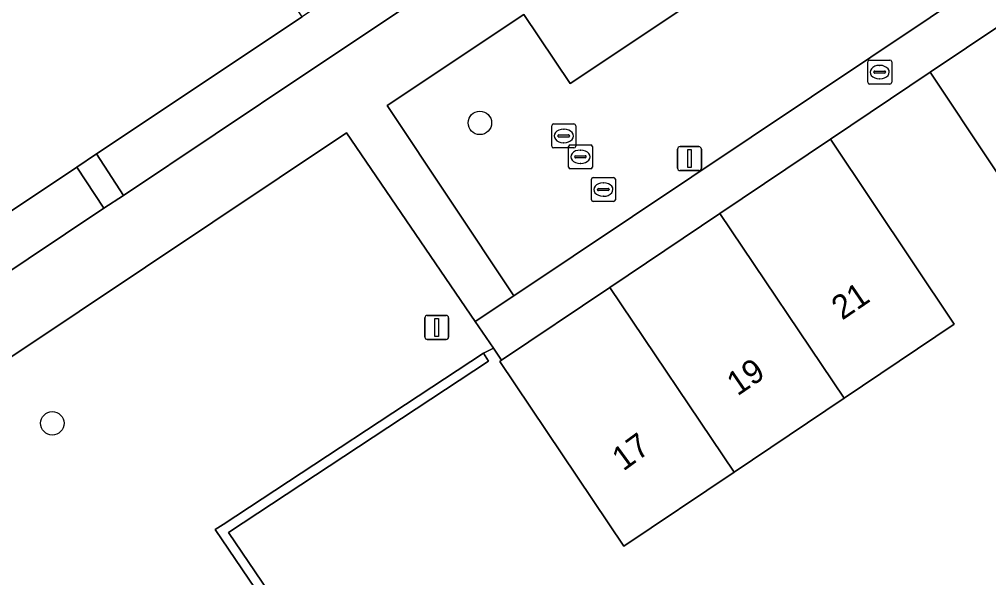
# Model space of a CAD drawing. Extents: x 158793 to 159888, y 384317 to 385256.
# Drawn here: x 158869.24 to 158909.67, y 384526.35 to 384549.65 of the extents above; entities that cross this region are included whole.
import ezdxf

# ---------------------------------------------------------------- set-up
doc = ezdxf.new("R2010")
doc.units = 0
for name, color, linetype in [('IMGEO_Boom', 7, 'Continuous'), ('IMGEO_Brandkraan', 7, 'Continuous'), ('IMGEO_Erf', 7, 'Continuous'), ('IMGEO_Groenvoorziening', 7, 'Continuous'), ('IMGEO_Haag', 7, 'Continuous'), ('IMGEO_Lichtmast', 7, 'Continuous'), ('IMGEO_Pand', 7, 'Continuous'), ('IMGEO_Pand_nummerreeks', 7, 'Continuous'), ('IMGEO_Rioolput', 7, 'Continuous'), ('IMGEO_Voetpad_gesloten', 7, 'Continuous'), ('IMGEO_Voetpad_halfverhard', 7, 'Continuous'), ('IMGEO_Voetpad_open', 7, 'Continuous')]:
    doc.layers.add(name, color=color, linetype=linetype)

msp = doc.modelspace()

# ---------------------------------------------------------------- linework, layer by layer
at = {"layer": 'IMGEO_Boom'}
for centre in [(158888.451, 384545.33), (158870.612, 384532.793)]:
    msp.add_circle(centre, 0.489, dxfattribs=at)
at = {"layer": 'IMGEO_Brandkraan'}
for p, q in [((158904.63, 384547.023), (158904.63, 384547.875)), ((158904.705, 384547.949), (158905.557, 384547.949)), ((158905.631, 384547.875), (158905.631, 384547.023)), ((158904.889, 384547.443), (158904.889, 384547.455)), ((158904.932, 384547.492), (158905.33, 384547.492)), ((158905.118, 384547.729), (158905.143, 384547.729)), ((158905.373, 384547.455), (158905.373, 384547.443)), ((158905.327, 384547.406), (158904.929, 384547.406)), ((158905.141, 384547.169), (158905.116, 384547.169)), ((158905.557, 384546.949), (158904.705, 384546.949))]:
    msp.add_line(p, q, dxfattribs=at)
for points in [[(158904.63, 384547.023), (158904.63, 384547.875)], [(158904.705, 384547.949), (158905.557, 384547.949)], [(158905.631, 384547.875), (158905.631, 384547.023)], [(158905.557, 384546.949), (158904.705, 384546.949)]]:
    msp.add_lwpolyline(points, dxfattribs=at)
for centre, radius, start, end in [((158904.707, 384547.873), 0.0765, 91.552, 178.448), ((158904.707, 384547.873), 0.0765, 91.552, 178.448), ((158905.555, 384547.873), 0.0765, 1.552, 88.448), ((158905.555, 384547.873), 0.0765, 1.552, 88.448), ((158904.929, 384547.452), 0.0403, 85.8775, 175.7526), ((158904.926, 384547.442), 0.0366, 178.938, 274.7102), ((158905.33, 384547.449), 0.043, 264.8664, 352.4533), ((158905.334, 384547.454), 0.0386, 1.7309, 96.639), ((158904.707, 384547.025), 0.0765, 181.552, 268.448), ((158904.707, 384547.025), 0.0765, 181.552, 268.448), ((158905.555, 384547.025), 0.0765, 271.552, 358.448), ((158905.555, 384547.025), 0.0765, 271.552, 358.448)]:
    msp.add_arc(centre, radius, start, end, dxfattribs=at)
for centre, major_axis, ratio, start_param, end_param in [((158905.117, 384547.449), (-0.387, 0.002), 0.722429, 4.712389, 7.853982), ((158905.142, 384547.449), (-0.39, 0.002), 0.717154, 1.570796, 4.712389)]:
    msp.add_ellipse(centre, major_axis=major_axis, ratio=ratio, start_param=start_param, end_param=end_param, dxfattribs=at)
at = {"layer": 'IMGEO_Erf'}
msp.add_lwpolyline([(158912.383, 384539.719), (158907.238, 384547.447), (158903.083, 384544.653), (158908.235, 384536.927), (158903.644, 384533.841), (158899.053, 384530.755), (158894.462, 384527.668), (158889.282, 384535.373), (158889.357, 384535.423), (158889.013, 384535.927), (158888.595, 384535.724), (158888.815, 384535.39), (158877.967, 384528.242), (158894.477, 384503.881)], dxfattribs=at)
at = {"layer": 'IMGEO_Groenvoorziening'}
for points in [[(158912.188, 384553.057), (158908.819, 384558.044), (158892.215, 384546.967), (158890.278, 384549.853), (158884.582, 384546.051), (158889.87, 384538.118)], [(158859.32, 384554.45), (158856.721, 384552.773), (158856.279, 384553.362), (158851.333, 384549.895), (158861.674, 384534.354), (158872.769, 384541.766), (158871.634, 384543.486), (158868.183, 384541.187)], [(158885.76, 384550.431), (158884.602, 384552.16), (158881.04, 384549.751), (158872.46, 384544.036), (158873.576, 384542.305), (158881.227, 384547.416)], [(158901.243, 384504.636), (158907.161, 384508.645), (158905.386, 384511.284), (158904.264, 384510.53), (158898.879, 384506.912), (158894.477, 384503.881), (158894.144, 384503.66), (158877.404, 384528.36), (158877.743, 384528.574), (158888.595, 384535.724), (158889.013, 384535.927), (158888.254, 384537.037), (158882.889, 384544.918), (158863.336, 384531.857), (158865.398, 384528.749), (158879.85, 384507.099), (158881.792, 384508.421), (158889.585, 384496.738)], [(158894.477, 384503.881), (158877.967, 384528.242), (158888.815, 384535.39), (158888.595, 384535.724), (158877.743, 384528.574), (158877.404, 384528.36), (158894.144, 384503.66)]]:
    msp.add_lwpolyline(points, close=True, dxfattribs=at)
at = {"layer": 'IMGEO_Haag'}
msp.add_lwpolyline([(158888.815, 384535.39), (158888.595, 384535.724), (158877.743, 384528.574), (158877.404, 384528.36), (158894.144, 384503.66), (158894.477, 384503.881), (158877.967, 384528.242)], close=True, dxfattribs=at)
at = {"layer": 'IMGEO_Lichtmast'}
for p, q in [((158896.7, 384543.439), (158896.7, 384544.239)), ((158896.7, 384544.239), (158896.7, 384543.439)), ((158896.8, 384544.339), (158897.59, 384544.339)), ((158897.59, 384544.339), (158896.8, 384544.339)), ((158897.69, 384544.239), (158897.69, 384543.439)), ((158897.69, 384543.439), (158897.69, 384544.239)), ((158897.59, 384543.339), (158896.8, 384543.339)), ((158896.8, 384543.339), (158897.59, 384543.339)), ((158886.157, 384536.394), (158886.157, 384537.194)), ((158886.157, 384537.194), (158886.157, 384536.394)), ((158886.257, 384537.294), (158887.047, 384537.294)), ((158887.047, 384537.294), (158886.257, 384537.294)), ((158887.147, 384537.194), (158887.147, 384536.394)), ((158887.147, 384536.394), (158887.147, 384537.194)), ((158887.047, 384536.294), (158886.257, 384536.294)), ((158886.257, 384536.294), (158887.047, 384536.294))]:
    msp.add_line(p, q, dxfattribs=at)
for points in [[(158897.12, 384544.214), (158897.27, 384544.214), (158897.27, 384543.464), (158897.12, 384543.464), (158897.12, 384544.214)], [(158886.577, 384537.169), (158886.727, 384537.169), (158886.727, 384536.419), (158886.577, 384536.419), (158886.577, 384537.169)]]:
    msp.add_lwpolyline(points, dxfattribs=at)
for centre, start, end in [((158896.8, 384544.239), 90, 180), ((158896.8, 384544.239), 90, 180), ((158897.59, 384544.239), 0, 90), ((158897.59, 384544.239), 360, 90), ((158896.8, 384543.439), 180, 270), ((158896.8, 384543.439), 180, 270), ((158897.59, 384543.439), 270, 0), ((158897.59, 384543.439), 270, 0), ((158886.257, 384537.194), 90, 180), ((158886.257, 384537.194), 90, 180), ((158887.047, 384537.194), 0, 90), ((158887.047, 384537.194), 360, 90), ((158886.257, 384536.394), 180, 270), ((158886.257, 384536.394), 180, 270), ((158887.047, 384536.394), 270, 0), ((158887.047, 384536.394), 270, 0)]:
    msp.add_arc(centre, 0.1, start, end, dxfattribs=at)
at = {"layer": 'IMGEO_Pand'}
msp.add_lwpolyline([(158855.089, 384557.324), (158856.243, 384555.552), (158856.8, 384555.439), (158858.085, 384556.298), (158859.32, 384554.45), (158868.183, 384541.187), (158871.634, 384543.486), (158872.46, 384544.036), (158881.04, 384549.751), (158878.397, 384553.717), (158892.571, 384563.159), (158895.186, 384559.32), (158897.236, 384560.707), (158894.671, 384564.558), (158907.106, 384572.842)], dxfattribs=at)
for points in [[(158911.747, 384550.473), (158907.238, 384547.447), (158912.383, 384539.719), (158916.94, 384542.749)], [(158903.644, 384533.841), (158908.235, 384536.927), (158903.083, 384544.653), (158898.464, 384541.547)], [(158893.873, 384538.46), (158899.053, 384530.755), (158903.644, 384533.841), (158898.464, 384541.547)], [(158893.873, 384538.46), (158889.357, 384535.423), (158889.282, 384535.373), (158894.462, 384527.668), (158899.053, 384530.755)]]:
    msp.add_lwpolyline(points, close=True, dxfattribs=at)
at = {"layer": 'IMGEO_Rioolput'}
for p, q in [((158891.448, 384544.358), (158891.448, 384545.21)), ((158891.523, 384545.284), (158892.375, 384545.284)), ((158891.936, 384545.064), (158891.961, 384545.064)), ((158892.449, 384545.21), (158892.449, 384544.358)), ((158891.707, 384544.778), (158891.707, 384544.79)), ((158892.145, 384544.741), (158891.747, 384544.741)), ((158891.75, 384544.827), (158892.148, 384544.827)), ((158892.191, 384544.79), (158892.191, 384544.778)), ((158892.375, 384544.284), (158891.523, 384544.284)), ((158891.959, 384544.504), (158891.934, 384544.504)), ((158892.146, 384543.488), (158892.146, 384544.34)), ((158892.221, 384544.414), (158893.073, 384544.414)), ((158892.634, 384544.194), (158892.659, 384544.194)), ((158893.147, 384544.34), (158893.147, 384543.488)), ((158892.405, 384543.908), (158892.405, 384543.92)), ((158892.843, 384543.871), (158892.445, 384543.871)), ((158892.448, 384543.957), (158892.846, 384543.957)), ((158892.889, 384543.92), (158892.889, 384543.908)), ((158893.073, 384543.414), (158892.221, 384543.414)), ((158892.657, 384543.634), (158892.632, 384543.634)), ((158893.177, 384543.049), (158894.029, 384543.049)), ((158893.102, 384542.123), (158893.102, 384542.975)), ((158893.404, 384542.592), (158893.802, 384542.592)), ((158893.59, 384542.829), (158893.615, 384542.829)), ((158894.103, 384542.975), (158894.103, 384542.123)), ((158893.361, 384542.543), (158893.361, 384542.555)), ((158893.799, 384542.506), (158893.401, 384542.506)), ((158893.613, 384542.269), (158893.588, 384542.269)), ((158893.845, 384542.555), (158893.845, 384542.543)), ((158894.029, 384542.049), (158893.177, 384542.049))]:
    msp.add_line(p, q, dxfattribs=at)
for points in [[(158891.448, 384544.358), (158891.448, 384545.21)], [(158891.523, 384545.284), (158892.375, 384545.284)], [(158892.449, 384545.21), (158892.449, 384544.358)], [(158892.375, 384544.284), (158891.523, 384544.284)], [(158892.146, 384543.488), (158892.146, 384544.34)], [(158892.221, 384544.414), (158893.073, 384544.414)], [(158893.147, 384544.34), (158893.147, 384543.488)], [(158893.073, 384543.414), (158892.221, 384543.414)], [(158893.177, 384543.049), (158894.029, 384543.049)], [(158893.102, 384542.123), (158893.102, 384542.975)], [(158894.103, 384542.975), (158894.103, 384542.123)], [(158894.029, 384542.049), (158893.177, 384542.049)]]:
    msp.add_lwpolyline(points, dxfattribs=at)
for centre, radius, start, end in [((158891.525, 384545.208), 0.0765, 91.552, 178.448), ((158891.525, 384545.208), 0.0765, 91.552, 178.448), ((158892.373, 384545.208), 0.0765, 1.552, 88.448), ((158892.373, 384545.208), 0.0765, 1.552, 88.448), ((158891.747, 384544.787), 0.0403, 85.8775, 175.7526), ((158891.744, 384544.777), 0.0366, 178.938, 274.7102), ((158892.148, 384544.784), 0.043, 264.8664, 352.4533), ((158892.152, 384544.789), 0.0386, 1.7309, 96.639), ((158891.525, 384544.36), 0.0765, 181.552, 268.448), ((158891.525, 384544.36), 0.0765, 181.552, 268.448), ((158892.223, 384544.338), 0.0765, 91.552, 178.448), ((158892.223, 384544.338), 0.0765, 91.552, 178.448), ((158892.373, 384544.36), 0.0765, 271.552, 358.448), ((158892.373, 384544.36), 0.0765, 271.552, 358.448), ((158893.071, 384544.338), 0.0765, 1.552, 88.448), ((158893.071, 384544.338), 0.0765, 1.552, 88.448), ((158892.445, 384543.917), 0.0403, 85.8775, 175.7526), ((158892.442, 384543.907), 0.0366, 178.938, 274.7102), ((158892.846, 384543.914), 0.043, 264.8664, 352.4533), ((158892.85, 384543.919), 0.0386, 1.7309, 96.639), ((158892.223, 384543.49), 0.0765, 181.552, 268.448), ((158892.223, 384543.49), 0.0765, 181.552, 268.448), ((158893.071, 384543.49), 0.0765, 271.552, 358.448), ((158893.071, 384543.49), 0.0765, 271.552, 358.448), ((158893.179, 384542.973), 0.0765, 91.552, 178.448), ((158893.179, 384542.973), 0.0765, 91.552, 178.448), ((158894.027, 384542.973), 0.0765, 1.552, 88.448), ((158894.027, 384542.973), 0.0765, 1.552, 88.448), ((158893.401, 384542.552), 0.0403, 85.8775, 175.7526), ((158893.806, 384542.554), 0.0386, 1.7309, 96.639), ((158893.398, 384542.542), 0.0366, 178.938, 274.7102), ((158893.802, 384542.549), 0.043, 264.8664, 352.4533), ((158893.179, 384542.125), 0.0765, 181.552, 268.448), ((158893.179, 384542.125), 0.0765, 181.552, 268.448), ((158894.027, 384542.125), 0.0765, 271.552, 358.448), ((158894.027, 384542.125), 0.0765, 271.552, 358.448)]:
    msp.add_arc(centre, radius, start, end, dxfattribs=at)
for centre, major_axis, ratio, start_param, end_param in [((158891.935, 384544.784), (-0.387, 0.002), 0.722429, 4.712389, 7.853982), ((158891.96, 384544.784), (-0.39, 0.002), 0.717154, 1.570796, 4.712389), ((158892.633, 384543.914), (-0.387, 0.002), 0.722429, 4.712389, 7.853982), ((158892.658, 384543.914), (-0.39, 0.002), 0.717154, 1.570796, 4.712389), ((158893.589, 384542.549), (-0.387, 0.002), 0.722429, 4.712389, 7.853982), ((158893.614, 384542.549), (-0.39, 0.002), 0.717154, 1.570796, 4.712389)]:
    msp.add_ellipse(centre, major_axis=major_axis, ratio=ratio, start_param=start_param, end_param=end_param, dxfattribs=at)
at = {"layer": 'IMGEO_Voetpad_gesloten'}
msp.add_lwpolyline([(158920.463, 384569.434), (158897.216, 384553.897), (158895.279, 384556.763), (158894.867, 384556.489), (158894.012, 384555.92), (158886.593, 384550.985), (158885.76, 384550.431), (158881.227, 384547.416), (158873.576, 384542.305), (158872.769, 384541.766), (158861.674, 384534.354), (158860.392, 384533.498), (158851.128, 384527.309), (158852.808, 384524.835), (158862.048, 384531.017), (158863.336, 384531.857), (158882.889, 384544.918), (158888.254, 384537.037), (158889.87, 384538.118), (158884.582, 384546.051), (158890.278, 384549.853), (158892.215, 384546.967), (158908.819, 384558.044), (158912.188, 384553.057)], dxfattribs=at)
at = {"layer": 'IMGEO_Voetpad_halfverhard'}
msp.add_lwpolyline([(158872.46, 384544.036), (158871.634, 384543.486), (158872.769, 384541.766), (158873.576, 384542.305)], close=True, dxfattribs=at)
at = {"layer": 'IMGEO_Voetpad_open'}
msp.add_lwpolyline([(158916.291, 384553.522), (158920.835, 384556.571), (158925.371, 384559.632), (158929.912, 384562.685), (158934.472, 384565.722), (158934.973, 384566.056), (158933.922, 384567.605), (158913.823, 384554.152), (158912.188, 384553.057), (158889.87, 384538.118), (158888.254, 384537.037), (158889.013, 384535.927), (158889.357, 384535.423), (158893.873, 384538.46), (158898.464, 384541.547), (158903.083, 384544.653), (158907.238, 384547.447), (158911.747, 384550.473)], close=True, dxfattribs=at)

# ---------------------------------------------------------------- texts
at = {"layer": 'IMGEO_Pand_nummerreeks'}
for s, rotation, p in [('21', 34.2954, (158903.565, 384537.073)), ('19', 34.4344, (158899.198, 384533.909)), ('17', 36.188, (158894.436, 384530.771))]:
    msp.add_text(s, height=1, rotation=rotation, dxfattribs=at).set_placement(p)

doc.saveas('drawing.dxf')
